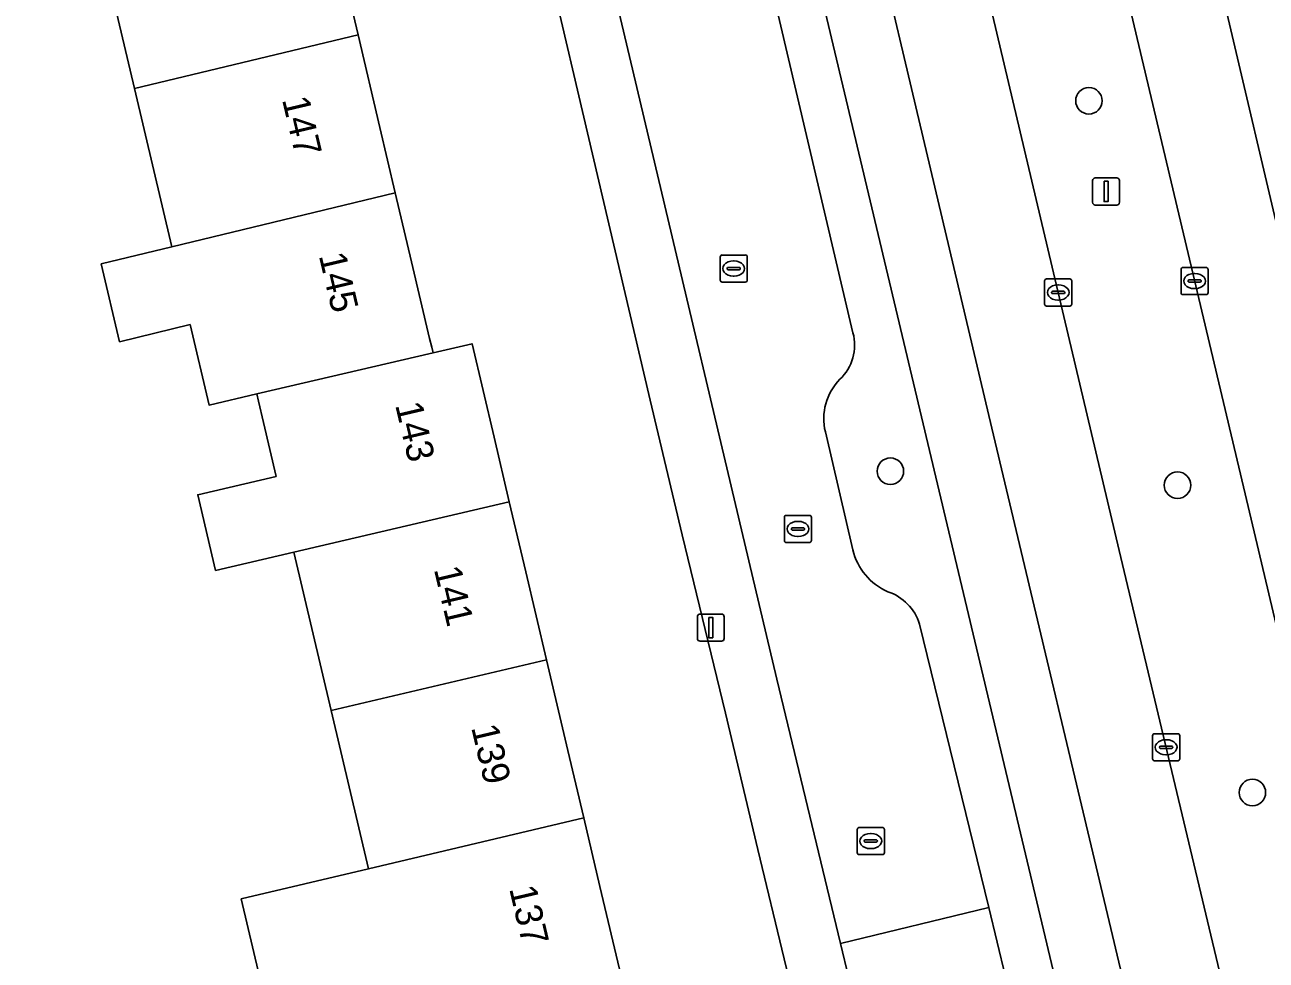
# Model space of a CAD drawing. Extents: x 158472 to 159562, y 388525 to 389606.
# Drawn here: x 159239.31 to 159285.1, y 388783.57 to 388818.07 of the extents above; entities that cross this region are included whole.
import ezdxf

# ---------------------------------------------------------------- set-up
doc = ezdxf.new("R2010")
doc.units = 0
for name, color, linetype in [('IMGEO_Berm_groen', 7, 'Continuous'), ('IMGEO_Boom', 7, 'Continuous'), ('IMGEO_Erf', 7, 'Continuous'), ('IMGEO_Kolk', 7, 'Continuous'), ('IMGEO_Lichtmast', 7, 'Continuous'), ('IMGEO_Pand', 7, 'Continuous'), ('IMGEO_Pand_nummerreeks', 7, 'Continuous'), ('IMGEO_Rijbaan_lokaal_gesloten', 7, 'Continuous'), ('IMGEO_Rijbaan_lokaal_open', 7, 'Continuous'), ('IMGEO_Voetpad_open', 7, 'Continuous')]:
    doc.layers.add(name, color=color, linetype=linetype)

msp = doc.modelspace()

# ---------------------------------------------------------------- linework, layer by layer
at = {"layer": 'IMGEO_Berm_groen'}
for points in [[(159277.901, 388827.843), (159276.343, 388834.412), (159270.29, 388859.938), (159269.541, 388863.127), (159266.797, 388874.809), (159261.846, 388873.649), (159264.636, 388861.977), (159271.366, 388833.818), (159271.51, 388833.21), (159279.673, 388798.682), (159283.502, 388782.632), (159288.208, 388762.614)], [(159277.616, 388773.955), (159279.332, 388774.364), (159277.906, 388780.397), (159273.326, 388799.622), (159265.691, 388831.762)], [(159293.018, 388764.082), (159289.528, 388778.742), (159284.536, 388799.838), (159277.901, 388827.843)], [(159266.481, 388821.067), (159269.854, 388806.707)], [(159268.836, 388803.051), (159269.846, 388798.699)], [(159272.312, 388795.966), (159274.86, 388785.507), (159275.483, 388782.951), (159277.604, 388774.247)]]:
    msp.add_lwpolyline(points, dxfattribs=at)
for centre, radius, start, end in [((159268.177, 388806.251), 1.738, 313.6185, 15.2161), ((159270.844, 388803.539), 2.066, 135.2625, 193.6588), ((159272.071, 388799.254), 2.293, 194.0067, 246.1287), ((159270.571, 388795.427), 1.822, 17.2172, 71.7146)]:
    msp.add_arc(centre, radius, start, end, dxfattribs=at)
at = {"layer": 'IMGEO_Boom'}
for centre in [(159278.558, 388815.265), (159271.234, 388801.602), (159281.826, 388801.087), (159284.587, 388789.753)]:
    msp.add_circle(centre, 0.489, dxfattribs=at)
at = {"layer": 'IMGEO_Erf'}
for points in [[(159273.151, 388759.428), (159266.341, 388787.656), (159265.157, 388792.677), (159263.557, 388799.256), (159262.381, 388804.22), (159256.456, 388829.466)], [(159248.639, 388780.102), (159247.291, 388785.829), (159251.986, 388786.94), (159250.611, 388792.784), (159249.238, 388798.618), (159246.346, 388797.943), (159245.69, 388800.734), (159248.581, 388801.41), (159248.113, 388803.399), (159247.929, 388804.182), (159247.866, 388804.451), (159246.105, 388804.04), (159245.405, 388807.009), (159242.804, 388806.38), (159242.128, 388809.249), (159244.728, 388809.879), (159243.353, 388815.712), (159241.977, 388821.544)], [(159250.82, 388821.015), (159251.601, 388817.699), (159252.406, 388814.285), (159252.974, 388811.876), (159253.575, 388809.328), (159254.242, 388806.501), (159254.317, 388806.181), (159254.367, 388805.969), (159255.805, 388806.305), (159256.618, 388802.854), (159257.179, 388800.473), (159257.789, 388797.888), (159258.551, 388794.652), (159259.34, 388791.305), (159259.927, 388788.818), (159260.524, 388786.285), (159261.303, 388782.977)]]:
    msp.add_lwpolyline(points, dxfattribs=at)
at = {"layer": 'IMGEO_Kolk'}
for p, q in [((159264.957, 388808.651), (159264.957, 388809.503)), ((159265.032, 388809.577), (159265.884, 388809.577)), ((159265.445, 388809.357), (159265.47, 388809.357)), ((159265.958, 388809.503), (159265.958, 388808.651)), ((159265.216, 388809.071), (159265.216, 388809.083)), ((159265.654, 388809.034), (159265.256, 388809.034)), ((159265.259, 388809.12), (159265.657, 388809.12)), ((159265.468, 388808.797), (159265.443, 388808.797)), ((159265.7, 388809.083), (159265.7, 388809.071)), ((159281.954, 388808.191), (159281.954, 388809.043)), ((159282.029, 388809.117), (159282.881, 388809.117)), ((159282.442, 388808.897), (159282.467, 388808.897)), ((159282.955, 388809.043), (159282.955, 388808.191)), ((159265.884, 388808.577), (159265.032, 388808.577)), ((159276.924, 388807.769), (159276.924, 388808.621)), ((159276.999, 388808.695), (159277.851, 388808.695)), ((159277.412, 388808.475), (159277.437, 388808.475)), ((159277.925, 388808.621), (159277.925, 388807.769)), ((159282.213, 388808.611), (159282.213, 388808.623)), ((159282.651, 388808.574), (159282.253, 388808.574)), ((159282.256, 388808.66), (159282.654, 388808.66)), ((159282.465, 388808.337), (159282.44, 388808.337)), ((159282.697, 388808.623), (159282.697, 388808.611)), ((159277.183, 388808.189), (159277.183, 388808.201)), ((159277.621, 388808.152), (159277.223, 388808.152)), ((159277.226, 388808.238), (159277.624, 388808.238)), ((159277.435, 388807.915), (159277.41, 388807.915)), ((159277.667, 388808.201), (159277.667, 388808.189)), ((159282.881, 388808.117), (159282.029, 388808.117)), ((159277.851, 388807.695), (159276.999, 388807.695)), ((159267.324, 388799.048), (159267.324, 388799.9)), ((159267.399, 388799.974), (159268.251, 388799.974)), ((159267.812, 388799.754), (159267.837, 388799.754)), ((159268.325, 388799.9), (159268.325, 388799.048)), ((159267.583, 388799.468), (159267.583, 388799.48)), ((159268.021, 388799.431), (159267.623, 388799.431)), ((159267.626, 388799.517), (159268.024, 388799.517)), ((159267.835, 388799.194), (159267.81, 388799.194)), ((159268.067, 388799.48), (159268.067, 388799.468)), ((159268.251, 388798.974), (159267.399, 388798.974)), ((159280.905, 388790.996), (159280.905, 388791.848)), ((159280.98, 388791.922), (159281.832, 388791.922)), ((159281.906, 388791.848), (159281.906, 388790.996)), ((159281.164, 388791.416), (159281.164, 388791.428)), ((159281.207, 388791.465), (159281.605, 388791.465)), ((159281.393, 388791.702), (159281.418, 388791.702)), ((159281.648, 388791.428), (159281.648, 388791.416)), ((159281.602, 388791.379), (159281.204, 388791.379)), ((159281.416, 388791.142), (159281.391, 388791.142)), ((159281.832, 388790.922), (159280.98, 388790.922)), ((159270.012, 388787.537), (159270.012, 388788.389)), ((159270.087, 388788.463), (159270.939, 388788.463)), ((159270.5, 388788.243), (159270.525, 388788.243)), ((159271.013, 388788.389), (159271.013, 388787.537)), ((159270.271, 388787.957), (159270.271, 388787.969)), ((159270.709, 388787.92), (159270.311, 388787.92)), ((159270.314, 388788.006), (159270.712, 388788.006)), ((159270.755, 388787.969), (159270.755, 388787.957)), ((159270.939, 388787.463), (159270.087, 388787.463)), ((159270.523, 388787.683), (159270.498, 388787.683))]:
    msp.add_line(p, q, dxfattribs=at)
for points in [[(159264.957, 388808.651), (159264.957, 388809.503)], [(159265.032, 388809.577), (159265.884, 388809.577)], [(159265.958, 388809.503), (159265.958, 388808.651)], [(159281.954, 388808.191), (159281.954, 388809.043)], [(159282.029, 388809.117), (159282.881, 388809.117)], [(159282.955, 388809.043), (159282.955, 388808.191)], [(159265.884, 388808.577), (159265.032, 388808.577)], [(159276.924, 388807.769), (159276.924, 388808.621)], [(159276.999, 388808.695), (159277.851, 388808.695)], [(159277.925, 388808.621), (159277.925, 388807.769)], [(159282.881, 388808.117), (159282.029, 388808.117)], [(159277.851, 388807.695), (159276.999, 388807.695)], [(159267.324, 388799.048), (159267.324, 388799.9)], [(159267.399, 388799.974), (159268.251, 388799.974)], [(159268.325, 388799.9), (159268.325, 388799.048)], [(159268.251, 388798.974), (159267.399, 388798.974)], [(159280.905, 388790.996), (159280.905, 388791.848)], [(159280.98, 388791.922), (159281.832, 388791.922)], [(159281.906, 388791.848), (159281.906, 388790.996)], [(159281.832, 388790.922), (159280.98, 388790.922)], [(159270.012, 388787.537), (159270.012, 388788.389)], [(159270.087, 388788.463), (159270.939, 388788.463)], [(159271.013, 388788.389), (159271.013, 388787.537)], [(159270.939, 388787.463), (159270.087, 388787.463)]]:
    msp.add_lwpolyline(points, dxfattribs=at)
for centre, radius, start, end in [((159265.034, 388809.501), 0.0765, 91.552, 178.448), ((159265.034, 388809.501), 0.0765, 91.552, 178.448), ((159265.882, 388809.501), 0.0765, 1.552, 88.448), ((159265.882, 388809.501), 0.0765, 1.552, 88.448), ((159265.256, 388809.08), 0.0403, 85.8775, 175.7526), ((159265.253, 388809.07), 0.0366, 178.938, 274.7102), ((159265.657, 388809.077), 0.043, 264.8664, 352.4533), ((159265.661, 388809.082), 0.0386, 1.7309, 96.639), ((159282.031, 388809.041), 0.0765, 91.552, 178.448), ((159282.031, 388809.041), 0.0765, 91.552, 178.448), ((159282.879, 388809.041), 0.0765, 1.552, 88.448), ((159282.879, 388809.041), 0.0765, 1.552, 88.448), ((159265.034, 388808.653), 0.0765, 181.552, 268.448), ((159265.034, 388808.653), 0.0765, 181.552, 268.448), ((159265.882, 388808.653), 0.0765, 271.552, 358.448), ((159265.882, 388808.653), 0.0765, 271.552, 358.448), ((159277.001, 388808.619), 0.0765, 91.552, 178.448), ((159277.001, 388808.619), 0.0765, 91.552, 178.448), ((159277.849, 388808.619), 0.0765, 1.552, 88.448), ((159277.849, 388808.619), 0.0765, 1.552, 88.448), ((159282.253, 388808.62), 0.0403, 85.8775, 175.7526), ((159282.25, 388808.61), 0.0366, 178.938, 274.7102), ((159282.654, 388808.617), 0.043, 264.8664, 352.4533), ((159282.658, 388808.622), 0.0386, 1.7309, 96.639), ((159277.223, 388808.198), 0.0403, 85.8775, 175.7526), ((159277.22, 388808.188), 0.0366, 178.938, 274.7102), ((159277.624, 388808.195), 0.043, 264.8664, 352.4533), ((159277.628, 388808.2), 0.0386, 1.7309, 96.639), ((159282.031, 388808.193), 0.0765, 181.552, 268.448), ((159282.031, 388808.193), 0.0765, 181.552, 268.448), ((159282.879, 388808.193), 0.0765, 271.552, 358.448), ((159282.879, 388808.193), 0.0765, 271.552, 358.448), ((159277.001, 388807.771), 0.0765, 181.552, 268.448), ((159277.001, 388807.771), 0.0765, 181.552, 268.448), ((159277.849, 388807.771), 0.0765, 271.552, 358.448), ((159277.849, 388807.771), 0.0765, 271.552, 358.448), ((159267.401, 388799.898), 0.0765, 91.552, 178.448), ((159267.401, 388799.898), 0.0765, 91.552, 178.448), ((159268.249, 388799.898), 0.0765, 1.552, 88.448), ((159268.249, 388799.898), 0.0765, 1.552, 88.448), ((159267.623, 388799.477), 0.0403, 85.8775, 175.7526), ((159267.62, 388799.467), 0.0366, 178.938, 274.7102), ((159268.024, 388799.474), 0.043, 264.8664, 352.4533), ((159268.028, 388799.479), 0.0386, 1.7309, 96.639), ((159267.401, 388799.05), 0.0765, 181.552, 268.448), ((159267.401, 388799.05), 0.0765, 181.552, 268.448), ((159268.249, 388799.05), 0.0765, 271.552, 358.448), ((159268.249, 388799.05), 0.0765, 271.552, 358.448), ((159280.982, 388791.846), 0.0765, 91.552, 178.448), ((159280.982, 388791.846), 0.0765, 91.552, 178.448), ((159281.83, 388791.846), 0.0765, 1.552, 88.448), ((159281.83, 388791.846), 0.0765, 1.552, 88.448), ((159281.204, 388791.425), 0.0403, 85.8775, 175.7526), ((159281.201, 388791.415), 0.0366, 178.938, 274.7102), ((159281.605, 388791.422), 0.043, 264.8664, 352.4533), ((159281.609, 388791.427), 0.0386, 1.7309, 96.639), ((159280.982, 388790.998), 0.0765, 181.552, 268.448), ((159280.982, 388790.998), 0.0765, 181.552, 268.448), ((159281.83, 388790.998), 0.0765, 271.552, 358.448), ((159281.83, 388790.998), 0.0765, 271.552, 358.448), ((159270.089, 388788.387), 0.0765, 91.552, 178.448), ((159270.089, 388788.387), 0.0765, 91.552, 178.448), ((159270.937, 388788.387), 0.0765, 1.552, 88.448), ((159270.937, 388788.387), 0.0765, 1.552, 88.448), ((159270.311, 388787.966), 0.0403, 85.8775, 175.7526), ((159270.308, 388787.956), 0.0366, 178.938, 274.7102), ((159270.712, 388787.963), 0.043, 264.8664, 352.4533), ((159270.716, 388787.968), 0.0386, 1.7309, 96.639), ((159270.089, 388787.539), 0.0765, 181.552, 268.448), ((159270.089, 388787.539), 0.0765, 181.552, 268.448), ((159270.937, 388787.539), 0.0765, 271.552, 358.448), ((159270.937, 388787.539), 0.0765, 271.552, 358.448)]:
    msp.add_arc(centre, radius, start, end, dxfattribs=at)
for centre, major_axis, ratio, start_param, end_param in [((159265.444, 388809.077), (-0.387, 0.002), 0.722429, 4.712389, 7.853982), ((159265.469, 388809.077), (-0.39, 0.002), 0.717154, 1.570796, 4.712389), ((159282.441, 388808.617), (-0.387, 0.002), 0.722429, 4.712389, 7.853982), ((159282.466, 388808.617), (-0.39, 0.002), 0.717154, 1.570796, 4.712389), ((159277.411, 388808.195), (-0.387, 0.002), 0.722429, 4.712389, 7.853982), ((159277.436, 388808.195), (-0.39, 0.002), 0.717154, 1.570796, 4.712389), ((159267.811, 388799.474), (-0.387, 0.002), 0.722429, 4.712389, 7.853982), ((159267.836, 388799.474), (-0.39, 0.002), 0.717154, 1.570796, 4.712389), ((159281.392, 388791.422), (-0.387, 0.002), 0.722429, 4.712389, 7.853982), ((159281.417, 388791.422), (-0.39, 0.002), 0.717154, 1.570796, 4.712389), ((159270.499, 388787.963), (-0.387, 0.002), 0.722429, 4.712389, 7.853982), ((159270.524, 388787.963), (-0.39, 0.002), 0.717154, 1.570796, 4.712389)]:
    msp.add_ellipse(centre, major_axis=major_axis, ratio=ratio, start_param=start_param, end_param=end_param, dxfattribs=at)
at = {"layer": 'IMGEO_Lichtmast'}
for p, q in [((159278.694, 388811.521), (159278.694, 388812.321)), ((159278.694, 388812.321), (159278.694, 388811.521)), ((159278.794, 388812.421), (159279.584, 388812.421)), ((159279.584, 388812.421), (159278.794, 388812.421)), ((159279.684, 388812.321), (159279.684, 388811.521)), ((159279.684, 388811.521), (159279.684, 388812.321)), ((159279.584, 388811.421), (159278.794, 388811.421)), ((159278.794, 388811.421), (159279.584, 388811.421)), ((159264.116, 388795.434), (159264.116, 388796.234)), ((159264.116, 388796.234), (159264.116, 388795.434)), ((159264.216, 388796.334), (159265.006, 388796.334)), ((159265.006, 388796.334), (159264.216, 388796.334)), ((159265.106, 388796.234), (159265.106, 388795.434)), ((159265.106, 388795.434), (159265.106, 388796.234)), ((159265.006, 388795.334), (159264.216, 388795.334)), ((159264.216, 388795.334), (159265.006, 388795.334))]:
    msp.add_line(p, q, dxfattribs=at)
for points in [[(159279.114, 388812.296), (159279.264, 388812.296), (159279.264, 388811.546), (159279.114, 388811.546), (159279.114, 388812.296)], [(159264.536, 388796.209), (159264.686, 388796.209), (159264.686, 388795.459), (159264.536, 388795.459), (159264.536, 388796.209)]]:
    msp.add_lwpolyline(points, dxfattribs=at)
for centre, start, end in [((159278.794, 388812.321), 90, 180), ((159278.794, 388812.321), 90, 180), ((159279.584, 388812.321), 0, 90), ((159279.584, 388812.321), 360, 90), ((159278.794, 388811.521), 180, 270), ((159278.794, 388811.521), 180, 270), ((159279.584, 388811.521), 270, 0), ((159279.584, 388811.521), 270, 0), ((159264.216, 388796.234), 90, 180), ((159264.216, 388796.234), 90, 180), ((159265.006, 388796.234), 0, 90), ((159265.006, 388796.234), 360, 90), ((159264.216, 388795.434), 180, 270), ((159264.216, 388795.434), 180, 270), ((159265.006, 388795.434), 270, 0), ((159265.006, 388795.434), 270, 0)]:
    msp.add_arc(centre, 0.1, start, end, dxfattribs=at)
at = {"layer": 'IMGEO_Pand'}
for points in [[(159250.23, 388823.516), (159241.977, 388821.544), (159243.353, 388815.712), (159251.601, 388817.699), (159250.82, 388821.015)], [(159252.974, 388811.876), (159252.406, 388814.285), (159251.601, 388817.699), (159243.353, 388815.712), (159244.728, 388809.879)], [(159252.974, 388811.876), (159244.728, 388809.879), (159242.128, 388809.249), (159242.804, 388806.38), (159245.405, 388807.009), (159246.105, 388804.04), (159247.866, 388804.451), (159254.367, 388805.969), (159254.317, 388806.181), (159254.242, 388806.501), (159253.575, 388809.328)], [(159254.367, 388805.969), (159247.866, 388804.451), (159247.929, 388804.182), (159248.113, 388803.399), (159248.581, 388801.41), (159245.69, 388800.734), (159246.346, 388797.943), (159249.238, 388798.618), (159257.179, 388800.473), (159256.618, 388802.854), (159255.805, 388806.305)], [(159250.611, 388792.784), (159258.551, 388794.652), (159257.789, 388797.888), (159257.179, 388800.473), (159249.238, 388798.618)], [(159250.611, 388792.784), (159251.986, 388786.94), (159259.927, 388788.818), (159259.34, 388791.305), (159258.551, 388794.652)], [(159260.524, 388786.285), (159259.927, 388788.818), (159251.986, 388786.94), (159247.291, 388785.829), (159248.639, 388780.102), (159251.837, 388780.854), (159251.861, 388780.752), (159259.966, 388782.662), (159261.303, 388782.977)]]:
    msp.add_lwpolyline(points, close=True, dxfattribs=at)
at = {"layer": 'IMGEO_Rijbaan_lokaal_gesloten'}
for points in [[(159239.311, 389027.03), (159242.913, 389005.102), (159246.77, 388983.007), (159252.032, 388955.946), (159255.765, 388938.112), (159261.434, 388912.543), (159265.14, 388896.851), (159270.668, 388873.441), (159274.326, 388857.952), (159279.715, 388835.25), (159286.319, 388807.116)], [(159285.132, 388760.501), (159274.982, 388803.196), (159268.084, 388832.358), (159258.627, 388872.238), (159243.098, 388939.791)], [(159249.806, 388898.745), (159253.55, 388882.862), (159256.234, 388871.462), (159258.029, 388864.014), (159260.868, 388852.063), (159265.691, 388831.762), (159273.326, 388799.622), (159277.906, 388780.397), (159279.332, 388774.364), (159281.519, 388765.117), (159283.612, 388756.249), (159285.084, 388750), (159287.643, 388739.131)], [(159286.319, 388807.116), (159279.715, 388835.25), (159276.343, 388834.412), (159277.901, 388827.843), (159284.536, 388799.838), (159289.528, 388778.742), (159293.018, 388764.082)], [(159288.208, 388762.614), (159283.502, 388782.632), (159279.673, 388798.682), (159271.51, 388833.21), (159268.084, 388832.358), (159274.982, 388803.196), (159285.132, 388760.501), (159292.436, 388729.776), (159299.002, 388702.154), (159302.196, 388688.085), (159301.738, 388687.977), (159299.905, 388687.548), (159299.937, 388687.413), (159304.249, 388669.003), (159304.775, 388666.773), (159306.683, 388667.26), (159310.673, 388668.277), (159309.54, 388673.08), (159309.432, 388673.446)]]:
    msp.add_lwpolyline(points, dxfattribs=at)
at = {"layer": 'IMGEO_Rijbaan_lokaal_open'}
for points in [[(159264.191, 388830.772), (159263.557, 388833.423), (159258.005, 388832.106), (159258.51, 388829.977), (159261.502, 388817.367), (159267.045, 388793.931), (159269.394, 388784.189), (159274.86, 388785.507), (159272.312, 388795.966)], [(159269.854, 388806.707), (159266.481, 388821.067)], [(159269.846, 388798.699), (159268.836, 388803.051)]]:
    msp.add_lwpolyline(points, dxfattribs=at)
msp.add_lwpolyline([(159269.394, 388784.189), (159270.01, 388781.632), (159275.483, 388782.951), (159274.86, 388785.507)], close=True, dxfattribs=at)
for centre, radius, start, end in [((159268.177, 388806.251), 1.738, 313.6185, 15.2161), ((159270.844, 388803.539), 2.066, 135.2625, 193.6588), ((159272.071, 388799.254), 2.293, 194.0067, 246.1287), ((159270.571, 388795.427), 1.822, 17.2172, 71.7146)]:
    msp.add_arc(centre, radius, start, end, dxfattribs=at)
at = {"layer": 'IMGEO_Voetpad_open'}
for points in [[(159254.595, 388846.477), (159253.133, 388846.145), (159248.287, 388845.046), (159244.254, 388862.616), (159243.653, 388862.478), (159246.3, 388850.982), (159247.021, 388847.913), (159247.715, 388844.776), (159247.923, 388843.835), (159252.844, 388844.898), (159254.136, 388839.326), (159255.312, 388834.339), (159256.456, 388829.466), (159262.381, 388804.22), (159263.557, 388799.256), (159265.157, 388792.677), (159266.341, 388787.656), (159273.151, 388759.428), (159273.781, 388756.462), (159274.798, 388756.715)], [(159287.643, 388739.131), (159285.084, 388750), (159283.612, 388756.249), (159283.093, 388756.097), (159282.991, 388756.446), (159281.704, 388756.171), (159275.289, 388759.739), (159270.01, 388781.632), (159269.394, 388784.189), (159267.045, 388793.931), (159261.502, 388817.367), (159258.51, 388829.977), (159258.005, 388832.106), (159257.395, 388834.675), (159254.595, 388846.477)]]:
    msp.add_lwpolyline(points, dxfattribs=at)

# ---------------------------------------------------------------- texts
at = {"layer": 'IMGEO_Pand_nummerreeks'}
for s, rotation, p in [('147', 283.2663, (159248.794, 388815.312)), ('145', 283.2638, (159250.15, 388809.558)), ('143', 283.2638, (159252.966, 388804.048)), ('141', 283.2633, (159254.395, 388797.991)), ('139', 283.2633, (159255.77, 388792.156)), ('137', 283.2638, (159257.171, 388786.211))]:
    msp.add_text(s, height=1, rotation=rotation, dxfattribs=at).set_placement(p)

doc.saveas('drawing.dxf')
